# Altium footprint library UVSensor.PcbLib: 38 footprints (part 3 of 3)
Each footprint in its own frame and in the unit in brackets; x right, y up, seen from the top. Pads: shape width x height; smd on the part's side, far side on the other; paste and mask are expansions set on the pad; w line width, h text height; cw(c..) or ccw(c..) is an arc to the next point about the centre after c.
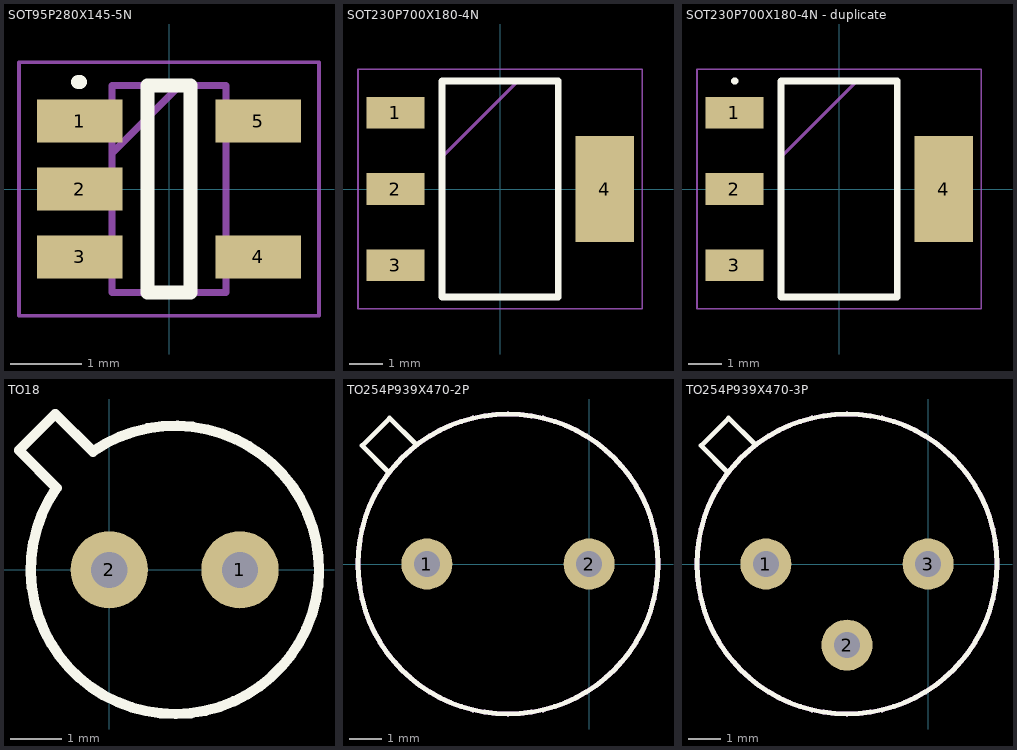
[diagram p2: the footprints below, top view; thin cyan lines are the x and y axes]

## SOT95P280X145-5N [mm]
pads (5):
  rect 1.2x0.6 smd: 1(-1.25,0.95) 2(-1.25,0) 3(-1.25,-0.95) 4(1.25,-0.95) 5(1.25,0.95)
Top Overlay:
  lines w0.2: -1.27,1.499 -1.245,1.499 ; -0.3,-1.45 0.3,-1.45 0.3,1.45 -0.3,1.45 -0.3,-1.45
Mechanical 13:
  lines w0.1: -0.8,0.5 0.15,1.45 ; -0.8,-1.45 0.8,-1.45 0.8,1.45 -0.8,1.45 -0.8,-1.45
  text ".Designator" at -1.145,1.765 h0.5
Mechanical 15:
  lines w0.05: -2.1,-1.775 2.1,-1.775 2.1,1.775 -2.1,1.775 -2.1,-1.775
3D body "OPA387DBVT.stp": height 1.2, standoff 0, extent -1.4,-1.45 1.4,1.45

## SOT230P700X180-4N [mm]
pads (4):
  rect 1.75x0.95 smd: 1(-3.15,2.3) 2(-3.15,0) 3(-3.15,-2.3)
  rect 1.75x3.2 smd: 4(3.15,0)
Top Overlay:
  lines w0.2: -1.75,-3.25 1.75,-3.25 1.75,3.25 -1.75,3.25 -1.75,-3.25
Mechanical 13:
  lines w0.1: -1.75,0.95 0.55,3.25 ; -1.75,-3.25 1.75,-3.25 1.75,3.25 -1.75,3.25 -1.75,-3.25
  text ".Designator" at -0.998,2.381 h0.76
Mechanical 15:
  lines w0.05: -4.275,-3.6 4.275,-3.6 4.275,3.6 -4.275,3.6 -4.275,-3.6
3D body "LM7805MP_NOPB.stp": height 1.8, standoff 0, extent -3.5,-3.25 3.5,3.25

## SOT230P700X180-4N - duplicate [mm]
pads (4):
  rect 1.75x0.95 smd: 1(-3.15,2.3) 2(-3.15,0) 3(-3.15,-2.3)
  rect 1.75x3.2 smd: 4(3.15,0)
Top Overlay:
  lines w0.2: -3.15,3.251 -3.124,3.251 ; -1.75,-3.25 -1.75,3.25 1.75,3.25 1.75,-3.25 -1.75,-3.25
Mechanical 13:
  lines w0.1: -1.75,0.95 0.55,3.25 ; -1.75,-3.25 -1.75,3.25 1.75,3.25 1.75,-3.25 -1.75,-3.25
  text ".Designator" at -1.65,3.517 h0.5
Mechanical 15:
  lines w0.05: -4.275,-3.6 -4.275,3.6 4.275,3.6 4.275,-3.6 -4.275,-3.6
3D body "TPS7B8433QDCYRQ1.stp": height 1.68, standoff 0, extent -3.5,-3.25 3.5,3.25

## TO18 [mm]
pads (2):
  round 1.5 hole 0.7: 1(2.54,0) 2(0,0)
Top Overlay:
  lines w0.2: -1.027,1.593 ccw(c1.275,0) -0.318,2.302 ; -1.021,1.589 -1.754,2.321 -1.046,3.029 -0.314,2.296
Mechanical 13:
  text ".Designator" at 0.127,1.481 h0.76
3D body "TO-18, short leads 4mm.step": height 4.48, standoff -3, extent -1.734,-2.925 4.2,3.009

## TO254P939X470-2P [mm]
pads (2):
  round 1.6 hole 0.813: 1(-5.08,0) 2(0,0)
Top Overlay:
  lines w0.152: -6.299,2.896 -7.112,3.708 -6.248,4.572 -5.436,3.759 ; -7.239,0 cw(c-2.54,0) 2.159,0 cw(c-2.54,0) -7.239,0
Mechanical 13:
  lines w0.152: -2.54,-4.699 ccw(c-2.54,0) -2.54,4.699 ccw(c-2.54,0) -2.54,-4.699
  text ".Designator" at -7,4.867 h0.5
3D body "User Library-TO-5 PACKAGE,IR-60.step": height 4.96, standoff -12.7, extent -7.112,-4.572 2.032,4.572

## TO254P939X470-3P [mm]
pads (3):
  round 1.6 hole 0.813: 1(-5.08,0) 2(-2.54,-2.54) 3(0,0)
Top Overlay:
  lines w0.152: -6.299,2.896 -7.112,3.708 -6.248,4.572 -5.436,3.759 ; -7.239,0 ccw(c-2.54,0) 2.159,0 ccw(c-2.54,0) -7.239,0
Mechanical 13:
  lines w0.152: -2.54,-4.699 cw(c-2.54,0) -2.54,4.699 cw(c-2.54,0) -2.54,-4.699
  text ".Designator" at -7,4.867 h0.5
3D body "User Library-TO-5 PACKAGE,IR-60.step": height 4.96, standoff -12.7, extent -7.112,-4.572 2.032,4.572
